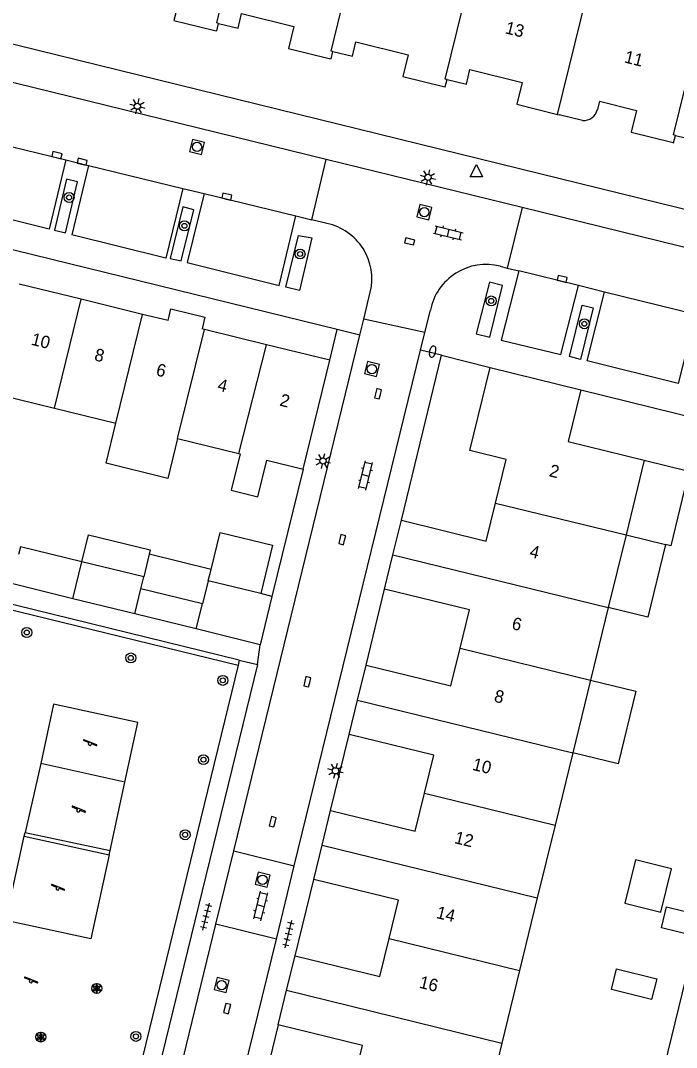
# Model space of a CAD drawing. Extents: x 128000 to 131008, y 398996 to 402500.
# Drawn here: x 128186 to 128238.6, y 399561.8 to 399644.1 of the extents above; entities that cross this region are included whole.
import ezdxf

# ---------------------------------------------------------------- set-up
doc = ezdxf.new("R2010")
doc.units = 0
for name, color, linetype in [('gg-afsc-hekwerk', 7, 'Continuous'), ('gg-afsc-muur', 7, 'Continuous'), ('gg-anno-huisnummerreeks BGT', 7, 'Continuous'), ('gg-bbg-bijgebouw', 7, 'Continuous'), ('gg-bbg-gedigitaliseerde bebouwing', 7, 'Continuous'), ('gg-bbg-gedigitaliseerde bijgebouw', 7, 'Continuous'), ('gg-bbg-hoofdgebouw', 7, 'Continuous'), ('gg-bbg-luifel en loopbrug', 7, 'Continuous'), ('gg-bbg-tussenscheiding', 7, 'Continuous'), ('gg-knt-verharding', 7, 'Continuous'), ('gg-knt-verharding nz', 7, 'Continuous'), ('gg-kntw-beschoeiing', 7, 'Continuous'), ('gt-grn-groengrens', 7, 'Continuous'), ('gt-grn-weggrens', 7, 'Continuous'), ('gt-symb-boom', 7, 'Continuous'), ('gt-symb-brandkraan', 7, 'Continuous'), ('gt-symb-klinker verharding', 7, 'Continuous'), ('gt-symb-kolk', 7, 'Continuous'), ('gt-symb-lichtmast', 7, 'Continuous'), ('gt-symb-rioolschacht', 7, 'Continuous'), ('gt-symb-solitaire heester', 7, 'Continuous'), ('gt-symb-speelvoorziening', 7, 'Continuous'), ('gt-symb-tegel verharding', 7, 'Continuous'), ('gt-symb-waterafsluiter', 7, 'Continuous')]:
    doc.layers.add(name, color=color, linetype=linetype)

# ---------------------------------------------------------------- blocks, each defined once
blk = doc.blocks.new('gt0-LMAST')
at = {"layer": 'gt-symb-lichtmast'}
for p, q in [((-0.182, 0.173), (-0.447, 0.438)), ((-0.005, 0.246), (-0.005, 0.621)), ((0.172, 0.173), (0.437, 0.438)), ((-0.255, -0.004), (-0.63, -0.004)), ((-0.182, -0.181), (-0.447, -0.446)), ((-0.005, -0.254), (-0.005, -0.629)), ((0.437, -0.446), (0.172, -0.181)), ((0.245, -0.004), (0.62, -0.004))]:
    blk.add_line(p, q, dxfattribs=at)
blk.add_circle((-0.005, -0.004), 0.25, dxfattribs=at)
blk = doc.blocks.new('gt0-TEG1')
at = {"layer": 'gt-symb-tegel verharding'}
for p, q in [((-1.125, 0), (1.125, 0)), ((-0.9, -0.25), (-0.9, 0.25)), ((-0.45, -0.25), (-0.45, 0.25)), ((0, -0.25), (0, 0.25)), ((0.45, -0.25), (0.45, 0.25)), ((0.9, -0.25), (0.9, 0.25))]:
    blk.add_line(p, q, dxfattribs=at)
blk = doc.blocks.new('gt0-KOLK')
at = {"layer": 'gt-symb-kolk'}
blk.add_lwpolyline([(0, 0), (0.375, 0), (0.375, 0.4), (-0.375, 0.4), (-0.375, 0), (0, 0)], dxfattribs=at)
blk = doc.blocks.new('gt0-BOOM')
at = {"layer": 'gt-symb-boom'}
for radius in [0.4, 0.2]:
    blk.add_circle((0, 0), radius, dxfattribs=at)
blk = doc.blocks.new('gt0-RS')
at = {"layer": 'gt-symb-rioolschacht'}
blk.add_lwpolyline([(-0.5, -0.5), (0.5, -0.5), (0.5, 0.5), (-0.5, 0.5)], close=True, dxfattribs=at)
blk.add_circle((0, 0), 0.375, dxfattribs=at)
blk = doc.blocks.new('gt0-BR')
at = {"layer": 'gt-symb-brandkraan'}
for centre, radius, start, end in [((-0.244, 0), 0.206, 107.56694, 252.43307), ((0.599, -2.664), 3, 106.89205, 107.56694), ((0, -0.691), 0.938, 73.10799, 106.89205), ((-0.599, -2.664), 3, 72.43309, 73.10799), ((0.244, 0), 0.206, 287.56695, 72.43309), ((0.599, 2.664), 3, 252.43307, 253.10797), ((0, 0.691), 0.938, 253.10797, 286.89206), ((-0.599, 2.664), 3, 286.89206, 287.56695)]:
    blk.add_arc(centre, radius, start, end, dxfattribs=at)
blk = doc.blocks.new('gt0-KL1')
at = {"layer": 'gt-symb-klinker verharding'}
for p, q in [((-1.15, 0.3), (1.15, 0.3)), ((-1, -0.3), (-1, 0.3)), ((-0.5, 0.3), (-0.5, 0.45)), ((0, -0.3), (0, 0.3)), ((0.5, 0.3), (0.5, 0.45)), ((1, -0.3), (1, 0.3)), ((-1.15, -0.3), (1.15, -0.3)), ((-0.5, -0.45), (-0.5, -0.3)), ((0.5, -0.45), (0.5, -0.3))]:
    blk.add_line(p, q, dxfattribs=at)
blk = doc.blocks.new('gt0-WAFSL')
at = {"layer": 'gt-symb-waterafsluiter'}
for p, q in [((-0.5, -0.333), (0, 0.667)), ((0, 0.667), (0.5, -0.333)), ((0.5, -0.333), (-0.5, -0.333))]:
    blk.add_line(p, q, dxfattribs=at)
blk = doc.blocks.new('gt0-SV')
at = {"layer": 'gt-symb-speelvoorziening'}
for p, q in [((-0.477, 0.255), (-0.08, 0.096)), ((0.542, -0.076), (-0.449, 0.324)), ((0.125, 0.014), (0.515, -0.143))]:
    blk.add_line(p, q, dxfattribs=at)
for centre, radius, start, end in [((-0.466, 0.291), 0.0369, 63.6251, 252.66016), ((-0.002, -0.005), 0.128, 127.68665, 8.59861), ((0.531, -0.111), 0.0363, 243.50852, 72.54358)]:
    blk.add_arc(centre, radius, start, end, dxfattribs=at)
blk = doc.blocks.new('gt0-SH')
at = {"layer": 'gt-symb-solitaire heester'}
blk.add_circle((0, 0), 0.4, dxfattribs=at)
for centre, start, end in [((-0.346, 0.2), 270, 30), ((-0.346, -0.2), 330, 90), ((0, 0.4), 210, 330), ((0.346, 0.2), 150, 270), ((0.346, -0.2), 90, 210), ((0, -0.4), 30, 150)]:
    blk.add_arc(centre, 0.4, start, end, dxfattribs=at)

msp = doc.modelspace()

# ---------------------------------------------------------------- linework, layer by layer
at = {"layer": 'gg-afsc-hekwerk'}
for p, q in [((128203.553, 399592.827), (128181.209, 399598.288)), ((128203.553, 399592.827), (128203.453, 399592.417)), ((128203.453, 399592.417), (128193.793, 399552.859))]:
    msp.add_line(p, q, dxfattribs=at)
at = {"layer": 'gg-afsc-muur'}
for p, q in [((128208.68, 399608.15), (128206.177, 399597.941)), ((128203.553, 399592.827), (128205.008, 399592.472))]:
    msp.add_line(p, q, dxfattribs=at)
at = {"layer": 'gg-bbg-bijgebouw'}
for p, q in [((128190.194, 399597.752), (128185.268, 399598.962)), ((128195.158, 399596.534), (128190.194, 399597.752)), ((128206.177, 399597.941), (128205.226, 399594.061)), ((128200.093, 399595.322), (128195.158, 399596.534)), ((128205.226, 399594.061), (128200.093, 399595.322))]:
    msp.add_line(p, q, dxfattribs=at)
at = {"layer": 'gg-bbg-gedigitaliseerde bebouwing'}
for p, q in [((128183.762, 399614.241), (128188.706, 399613.032)), ((128188.706, 399613.032), (128193.65, 399611.822)), ((128198.594, 399610.612), (128203.528, 399609.404))]:
    msp.add_line(p, q, dxfattribs=at)
for points in [[(128198.594, 399610.612), (128197.809, 399607.406), (128192.865, 399608.617), (128193.65, 399611.822)], [(128203.528, 399609.404), (128203.624, 399609.381), (128202.91, 399606.46)]]:
    msp.add_lwpolyline(points, dxfattribs=at)
at = {"layer": 'gg-bbg-gedigitaliseerde bijgebouw'}
for p, q in [((128195.882, 399599.503), (128190.924, 399600.71)), ((128195.648, 399598.545), (128195.882, 399599.503)), ((128201.064, 399599.195), (128200.606, 399597.339)), ((128205.278, 399598.161), (128201.064, 399599.195)), ((128200.606, 399597.339), (128195.648, 399598.545)), ((128206.177, 399597.941), (128205.278, 399598.161))]:
    msp.add_line(p, q, dxfattribs=at)
for points in [[(128190.924, 399600.71), (128185.986, 399601.912), (128185.834, 399601.287)], [(128237.859, 399573.029), (128240.481, 399572.387), (128240.072, 399570.716), (128237.45, 399571.358), (128237.859, 399573.029)], [(128233.827, 399568.055), (128237.059, 399567.264), (128236.654, 399565.607), (128233.422, 399566.398), (128233.827, 399568.055)]]:
    msp.add_lwpolyline(points, dxfattribs=at)
at = {"layer": 'gg-bbg-hoofdgebouw'}
for p, q in [((128232.458, 399637.649), (128232.298, 399636.996)), ((128229.098, 399636.605), (128229.24, 399636.57)), ((128231.095, 399636.117), (128229.24, 399636.57)), ((128190.863, 399621.767), (128185.892, 399622.984)), ((128195.786, 399620.562), (128190.863, 399621.767)), ((128197.831, 399620.061), (128195.786, 399620.562)), ((128200.767, 399619.342), (128200.563, 399619.392)), ((128205.728, 399618.127), (128200.767, 399619.342)), ((128210.82, 399616.88), (128205.728, 399618.127)), ((128208.68, 399608.15), (128210.82, 399616.88)), ((128223.68, 399616.29), (128230.96, 399614.51)), ((128236.06, 399608.86), (128234.595, 399602.871)), ((128215.89, 399601.258), (128216.57, 399604.04)), ((128234.595, 399602.871), (128233.17, 399597.046)), ((128215.22, 399598.52), (128215.89, 399601.258)), ((128233.17, 399597.046), (128231.745, 399591.221)), ((128213.041, 399589.608), (128213.73, 399592.42)), ((128231.745, 399591.221), (128230.32, 399585.396)), ((128212.371, 399586.87), (128213.041, 399589.608)), ((128230.32, 399585.396), (128228.896, 399579.573)), ((128210.204, 399577.987), (128210.88, 399580.76)), ((128228.896, 399579.573), (128227.471, 399573.748)), ((128209.53, 399575.22), (128210.204, 399577.987)), ((128227.471, 399573.748), (128226.045, 399567.922)), ((128207.35, 399566.349), (128208.03, 399569.1)), ((128226.045, 399567.922), (128224.618, 399562.088)), ((128206.66, 399563.56), (128207.35, 399566.349)), ((128224.618, 399562.088), (128223.189, 399556.244))]:
    msp.add_line(p, q, dxfattribs=at)
for points in [[(128192.66, 399646.17), (128194.23, 399645.78), (128194.52, 399646.95), (128198.751, 399645.91), (128198.31, 399644.14), (128201.595, 399643.335)], [(128201.595, 399643.335), (128201.74, 399643.3), (128201.89, 399643.901)], [(128201.89, 399643.901), (128203.45, 399643.52), (128203.74, 399644.69), (128207.94, 399643.66), (128207.51, 399641.9), (128210.777, 399641.095)], [(128211.07, 399641.65), (128212.63, 399641.27), (128212.91, 399642.42), (128217.1, 399641.39), (128216.681, 399639.65), (128219.935, 399638.846)], [(128210.777, 399641.095), (128210.92, 399641.06), (128211.07, 399641.65)], [(128220.23, 399639.4), (128221.78, 399639.02), (128222.07, 399640.19), (128226.26, 399639.16), (128225.83, 399637.41), (128229.098, 399636.605)], [(128219.935, 399638.846), (128220.08, 399638.81), (128220.23, 399639.4)], [(128232.458, 399637.649), (128235.431, 399636.92), (128235.001, 399635.17), (128238.27, 399634.365)], [(128238.56, 399634.92), (128240.12, 399634.53), (128240.4, 399635.68), (128244.591, 399634.64), (128244.16, 399632.89), (128247.433, 399632.086)], [(128238.27, 399634.365), (128238.41, 399634.33), (128238.56, 399634.92)], [(128197.831, 399620.061), (128198.062, 399621.003), (128200.796, 399620.342), (128200.563, 399619.392)], [(128224.123, 399605.423), (128224.98, 399608.93), (128222.06, 399609.64), (128223.68, 399616.29)], [(128230.96, 399614.51), (128229.94, 399610.35), (128236.06, 399608.86)], [(128202.91, 399606.46), (128205.04, 399605.93), (128205.76, 399608.86), (128208.68, 399608.15)], [(128216.57, 399604.04), (128223.38, 399602.38), (128224.123, 399605.423)], [(128221.272, 399593.797), (128222.02, 399596.86), (128215.22, 399598.52)], [(128213.73, 399592.42), (128220.53, 399590.76), (128221.272, 399593.797)], [(128218.426, 399582.157), (128219.17, 399585.21), (128212.371, 399586.87)], [(128210.88, 399580.76), (128217.68, 399579.1), (128218.426, 399582.157)], [(128215.577, 399570.488), (128216.33, 399573.56), (128209.53, 399575.22)], [(128208.03, 399569.1), (128214.83, 399567.44), (128215.577, 399570.488)], [(128212.703, 399558.823), (128213.45, 399561.9), (128206.66, 399563.56)]]:
    msp.add_lwpolyline(points, dxfattribs=at)
msp.add_arc((128231.199, 399637.237), 1.125, 264.69767, 347.61154, dxfattribs=at)
at = {"layer": 'gg-bbg-luifel en loopbrug'}
for p, q in [((128234.595, 399602.871), (128237.767, 399602.096)), ((128196.323, 399601.311), (128195.882, 399599.503)), ((128201.285, 399600.102), (128196.323, 399601.311)), ((128201.064, 399599.195), (128201.285, 399600.102))]:
    msp.add_line(p, q, dxfattribs=at)
for points in [[(128236.06, 399608.86), (128239.646, 399607.984), (128238.183, 399601.995), (128237.767, 399602.096)], [(128190.924, 399600.71), (128191.451, 399602.874), (128196.409, 399601.666), (128196.323, 399601.311)], [(128201.285, 399600.102), (128202.008, 399603.071), (128206.224, 399602.044), (128205.278, 399598.161)], [(128237.767, 399602.096), (128236.344, 399596.271), (128233.17, 399597.046)], [(128231.745, 399591.221), (128235.389, 399590.331), (128233.966, 399584.506), (128230.32, 399585.396)], [(128235.344, 399576.795), (128234.495, 399573.325), (128237.394, 399572.616), (128238.243, 399576.085), (128235.344, 399576.795)]]:
    msp.add_lwpolyline(points, dxfattribs=at)
at = {"layer": 'gg-bbg-tussenscheiding'}
for p, q in [((128188.706, 399613.032), (128190.863, 399621.767)), ((128193.65, 399611.822), (128195.786, 399620.562)), ((128198.594, 399610.612), (128200.767, 399619.342)), ((128203.528, 399609.404), (128205.728, 399618.127)), ((128224.123, 399605.423), (128234.595, 399602.871)), ((128215.89, 399601.258), (128233.17, 399597.046)), ((128190.194, 399597.752), (128190.924, 399600.71)), ((128195.158, 399596.534), (128195.648, 399598.545)), ((128200.093, 399595.322), (128200.606, 399597.339)), ((128221.272, 399593.797), (128231.745, 399591.221)), ((128213.041, 399589.608), (128230.32, 399585.396)), ((128218.426, 399582.157), (128228.896, 399579.573)), ((128210.204, 399577.987), (128227.471, 399573.748)), ((128215.577, 399570.488), (128226.045, 399567.922)), ((128207.35, 399566.349), (128224.618, 399562.088))]:
    msp.add_line(p, q, dxfattribs=at)
for points in [[(128201.89, 399643.901), (128201.743, 399643.937), (128204.124, 399653.62), (128204.269, 399653.584)], [(128211.07, 399641.65), (128210.922, 399641.686), (128213.294, 399651.356), (128213.44, 399651.32)], [(128229.098, 399636.605), (128232.36, 399649.85), (128232.482, 399649.82)], [(128220.23, 399639.4), (128220.08, 399639.437), (128222.457, 399649.115), (128222.6, 399649.08)], [(128238.56, 399634.92), (128238.416, 399634.956), (128240.797, 399644.618), (128240.95, 399644.58)]]:
    msp.add_lwpolyline(points, dxfattribs=at)
at = {"layer": 'gg-knt-verharding'}
for p, q in [((128258.441, 399624.279), (128163.514, 399647.59)), ((128210.514, 399632.989), (128161.155, 399645.107)), ((128211.42, 399619.34), (128158.01, 399632.42)), ((128189.64, 399632.949), (128191.442, 399632.51)), ((128191.442, 399632.51), (128190.107, 399626.931)), ((128209.369, 399628.147), (128210.514, 399632.989)), ((128226.271, 399629.121), (128210.514, 399632.989)), ((128199.012, 399630.668), (128200.732, 399630.249)), ((128226.271, 399629.121), (128225.061, 399624.279)), ((128257.733, 399621.397), (128226.271, 399629.121)), ((128208.087, 399628.459), (128209.369, 399628.147)), ((128210.59, 399627.85), (128209.369, 399628.147)), ((128224.49, 399624.42), (128225.061, 399624.279)), ((128225.061, 399624.279), (128226.005, 399624.046)), ((128232.868, 399622.354), (128230.78, 399622.868)), ((128213.541, 399620.182), (128214.071, 399622.352)), ((128218.451, 399619.098), (128218.891, 399620.892)), ((128213.227, 399618.895), (128213.541, 399620.182)), ((128218.451, 399619.098), (128213.541, 399620.182)), ((128210.82, 399616.88), (128211.42, 399619.34)), ((128203.116, 399577.526), (128213.227, 399618.895)), ((128218.107, 399617.693), (128218.451, 399619.098)), ((128207.966, 399576.322), (128218.107, 399617.693)), ((128216.57, 399604.04), (128219.79, 399617.28)), ((128219.79, 399617.28), (128223.68, 399616.29)), ((128230.96, 399614.51), (128245.953, 399610.824)), ((128213.73, 399592.42), (128215.22, 399598.52)), ((128205.008, 399592.472), (128195.231, 399552.506)), ((128210.88, 399580.76), (128212.371, 399586.87)), ((128187.614, 399584.544), (128186.355, 399578.993)), ((128194.371, 399583.047), (128187.614, 399584.544)), ((128193.186, 399577.545), (128194.371, 399583.047)), ((128186.297, 399578.705), (128186.355, 399578.993)), ((128186.355, 399578.993), (128193.186, 399577.545)), ((128186.297, 399578.705), (128193.112, 399577.208)), ((128193.112, 399577.208), (128191.633, 399570.474)), ((128193.112, 399577.208), (128193.186, 399577.545)), ((128201.678, 399571.644), (128203.116, 399577.526)), ((128203.116, 399577.526), (128207.966, 399576.322)), ((128206.527, 399570.454), (128207.966, 399576.322)), ((128208.03, 399569.1), (128209.53, 399575.22)), ((128190.091, 399524.233), (128201.678, 399571.644)), ((128206.527, 399570.454), (128201.678, 399571.644)), ((128200.476, 399545.767), (128206.527, 399570.454))]:
    msp.add_line(p, q, dxfattribs=at)
for points in [[(128189.64, 399632.949), (128188.279, 399627.384), (128180.981, 399629.222), (128182.311, 399634.732)], [(128190.569, 399631.179), (128189.688, 399631.403), (128188.712, 399627.304), (128189.589, 399627.096), (128190.569, 399631.179)], [(128199.012, 399630.668), (128197.664, 399625.077), (128190.107, 399626.931)], [(128200.732, 399630.249), (128199.379, 399624.711), (128206.752, 399622.888), (128208.087, 399628.459)], [(128199.893, 399628.949), (128199.023, 399629.18), (128197.992, 399625.033), (128198.89, 399624.86), (128199.893, 399628.949)], [(128208.316, 399626.899), (128209.376, 399626.691), (128208.394, 399622.488), (128207.296, 399622.751), (128208.316, 399626.899)], [(128226.005, 399624.046), (128224.581, 399618.496), (128229.375, 399617.349), (128230.78, 399622.868)], [(128224.669, 399622.878), (128223.628, 399623.132), (128222.563, 399619.006), (128223.664, 399618.737), (128224.669, 399622.878)], [(128240.163, 399620.555), (128238.78, 399615.009), (128231.489, 399616.827), (128232.868, 399622.354)], [(128231.072, 399621.305), (128231.971, 399621.097), (128230.939, 399616.938), (128230.057, 399617.172), (128231.072, 399621.305)], [(128194.371, 399583.047), (128195.396, 399587.829), (128188.639, 399589.292), (128187.614, 399584.544)], [(128191.633, 399570.474), (128184.823, 399571.935), (128186.297, 399578.705)], [(128206.66, 399563.56), (128203.45, 399550.37), (128206.715, 399549.552)]]:
    msp.add_lwpolyline(points, dxfattribs=at)
for centre, radius, start, end in [((128209.645, 399623.401), 4.548, 346.66901, 78.01001), ((128223.36, 399620.007), 4.556, 75.63483, 168.79626)]:
    msp.add_arc(centre, radius, start, end, dxfattribs=at)
at = {"layer": 'gg-knt-verharding nz'}
for p, q in [((128182.311, 399634.732), (128189.64, 399632.949)), ((128191.442, 399632.51), (128199.012, 399630.668)), ((128200.732, 399630.249), (128208.087, 399628.459)), ((128230.78, 399622.868), (128226.005, 399624.046)), ((128240.163, 399620.555), (128232.868, 399622.354))]:
    msp.add_line(p, q, dxfattribs=at)
at = {"layer": 'gg-kntw-beschoeiing'}
msp.add_lwpolyline([(128250.37, 399602.43), (128247.53, 399600.63), (128233.46, 399543.031)], dxfattribs=at)
at = {"layer": 'gt-grn-groengrens'}
msp.add_lwpolyline([(128174.493, 399583.51), (128175.194, 399583.34), (128178.789, 399598.441), (128203.453, 399592.417)], dxfattribs=at)
at = {"layer": 'gt-grn-weggrens'}
for p, q in [((128213.227, 399618.895), (128211.42, 399619.34)), ((128219.79, 399617.28), (128218.107, 399617.693)), ((128205.008, 399592.472), (128205.226, 399594.061))]:
    msp.add_line(p, q, dxfattribs=at)

# ---------------------------------------------------------------- block references
at = {"layer": 'gt-symb-boom'}
for p in [(128189.888, 399629.937), (128199.147, 399627.662), (128208.431, 399625.402), (128223.777, 399621.638), (128231.252, 399619.803), (128186.491, 399595.041), (128194.845, 399593)]:
    msp.add_blockref('gt0-BOOM', p, dxfattribs=at)
for p, rotation in [((128202.23, 399591.202), -13.716469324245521), ((128200.676, 399584.839), -13.71646932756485), ((128199.205, 399578.816), -13.716469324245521), ((128195.255, 399562.641), -13.716469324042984)]:
    msp.add_blockref('gt0-BOOM', p, dxfattribs=dict(at, rotation=rotation))
at = {"layer": 'gt-symb-brandkraan', "rotation": 76.22785456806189}
msp.add_blockref('gt0-BR', (128219.073, 399617.575), dxfattribs=at)
at = {"layer": 'gt-symb-klinker verharding'}
for p, rotation in [((128220.331, 399627.094), -13.702889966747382), ((128213.692, 399607.634), 76.28353067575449), ((128205.271, 399573.112), 76.29711003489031)]:
    msp.add_blockref('gt0-KL1', p, dxfattribs=dict(at, rotation=rotation))
at = {"layer": 'gt-symb-kolk'}
for p, rotation in [((128188.862, 399633.139), -13.772145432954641), ((128190.892, 399632.608), -14.119602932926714), ((128202.506, 399629.81), -13.772145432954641), ((128217.185, 399626.222), -13.772145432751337), ((128229.423, 399623.213), -13.77214542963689), ((128214.88, 399614.144), 76.22785456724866), ((128212.01, 399602.439), 76.22785456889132), ((128209.204, 399591.04), 76.22785456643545), ((128206.425, 399579.813), 76.22785456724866), ((128202.774, 399564.823), 76.22785456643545)]:
    msp.add_blockref('gt0-KOLK', p, dxfattribs=dict(at, rotation=rotation))
at = {"layer": 'gt-symb-lichtmast'}
for p, rotation in [((128195.379, 399637.26), -13.772145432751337), ((128218.703, 399631.546), -13.772145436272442), ((128210.261, 399608.8), 76.22785456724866), ((128211.274, 399583.952), 76.22785456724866)]:
    msp.add_blockref('gt0-LMAST', p, dxfattribs=dict(at, rotation=rotation))
at = {"layer": 'gt-symb-rioolschacht'}
for p, rotation in [((128200.16, 399633.99), -13.772145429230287), ((128218.405, 399628.761), -13.772145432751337), ((128214.198, 399616.171), -13.77214543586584), ((128205.421, 399575.207), 76.17220496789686), ((128202.14, 399566.757), 76.17220496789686)]:
    msp.add_blockref('gt0-RS', p, dxfattribs=dict(at, rotation=rotation))
at = {"layer": 'gt-symb-solitaire heester'}
for p in [(128192.115, 399566.489), (128187.619, 399562.591)]:
    msp.add_blockref('gt0-SH', p, dxfattribs=at)
at = {"layer": 'gt-symb-speelvoorziening'}
for p in [(128191.556, 399586.115), (128190.633, 399580.782), (128188.968, 399574.511), (128186.814, 399567.077)]:
    msp.add_blockref('gt0-SV', p, dxfattribs=at)
at = {"layer": 'gt-symb-tegel verharding'}
for p, rotation in [((128200.901, 399572.249), 76.28353067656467), ((128207.491, 399570.839), 76.28353067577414)]:
    msp.add_blockref('gt0-TEG1', p, dxfattribs=dict(at, rotation=rotation))
at = {"layer": 'gt-symb-waterafsluiter'}
msp.add_blockref('gt0-WAFSL', (128222.587, 399631.924), dxfattribs=at)

# ---------------------------------------------------------------- texts
at = {"layer": 'gg-anno-huisnummerreeks BGT'}
for s, rotation, p in [('13', 346.2, (128224.834, 399643.114)), ('11', 346.2, (128234.394, 399640.778)), ('10', 346.2, (128186.782, 399618.133)), ('8', 346.2, (128191.856, 399616.891)), ('6', 346.2, (128196.807, 399615.679)), ('4', 346.2, (128201.743, 399614.47)), ('2', 346.2, (128206.737, 399613.247)), ('2', 346.3, (128228.371, 399607.585)), ('4', 346.3, (128226.788, 399601.111)), ('6', 346.3, (128225.364, 399595.329)), ('8', 346.3, (128223.942, 399589.509)), ('10', 346.3, (128222.202, 399584.031)), ('12', 346.3, (128220.766, 399578.152)), ('14', 346.2, (128219.302, 399572.149)), ('16', 346.2, (128217.932, 399566.556))]:
    msp.add_text(s, height=1, rotation=rotation, dxfattribs=at).set_placement(p)

doc.saveas('drawing.dxf')
